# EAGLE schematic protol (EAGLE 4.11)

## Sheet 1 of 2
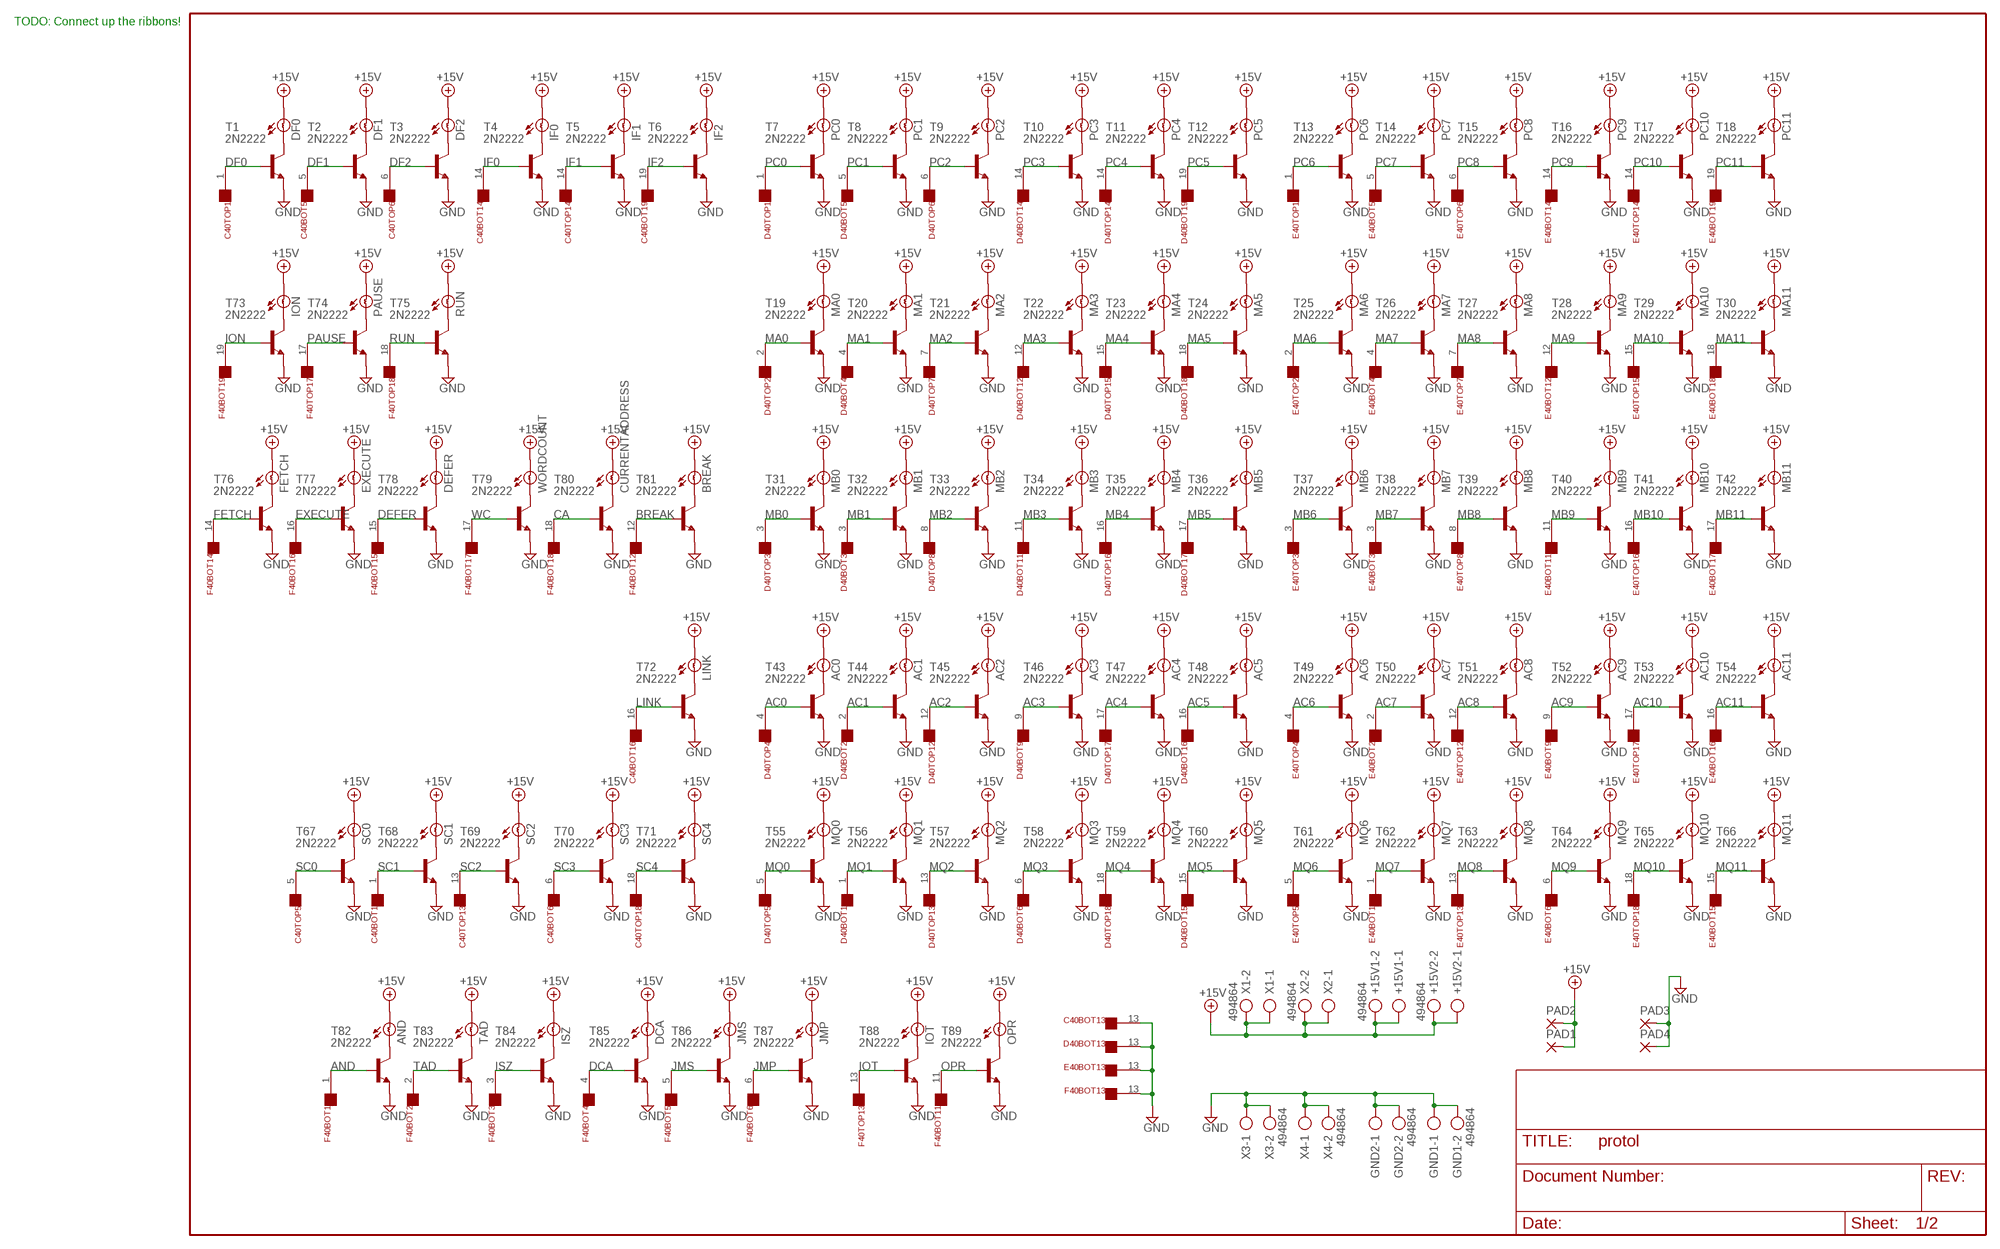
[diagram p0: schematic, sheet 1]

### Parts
+15V1  494864  AK500/2  [AK500/2]
+15V2  494864  AK500/2  [AK500/2]
AC0  BULB  [BULB]
AC1  BULB  [BULB]
AC2  BULB  [BULB]
AC3  BULB  [BULB]
AC4  BULB  [BULB]
AC5  BULB  [BULB]
AC6  BULB  [BULB]
AC7  BULB  [BULB]
AC8  BULB  [BULB]
AC9  BULB  [BULB]
AC10  BULB  [BULB]
AC11  BULB  [BULB]
AND  BULB  [BULB]
BREAK  BULB  [BULB]
C40BOT  FLEX19  [FLEX19]
C40TOP  FLEX19  [FLEX19]
CURRENTADDRESS  BULB  [BULB]
D40BOT  FLEX19  [FLEX19]
D40TOP  FLEX19  [FLEX19]
DCA  BULB  [BULB]
DEFER  BULB  [BULB]
DF0  BULB  [BULB]
DF1  BULB  [BULB]
DF2  BULB  [BULB]
E40BOT  FLEX19  [FLEX19]
E40TOP  FLEX19  [FLEX19]
EXECUTE  BULB  [BULB]
F40BOT  FLEX19  [FLEX19]
F40TOP  FLEX19  [FLEX19]
FETCH  BULB  [BULB]
GND1  494864  AK500/2  [AK500/2]
GND2  494864  AK500/2  [AK500/2]
IF0  BULB  [BULB]
IF1  BULB  [BULB]
IF2  BULB  [BULB]
ION  BULB  [BULB]
IOT  BULB  [BULB]
ISZ  BULB  [BULB]
JMP  BULB  [BULB]
JMS  BULB  [BULB]
LINK  BULB  [BULB]
MA0  BULB  [BULB]
MA1  BULB  [BULB]
MA2  BULB  [BULB]
MA3  BULB  [BULB]
MA4  BULB  [BULB]
MA5  BULB  [BULB]
MA6  BULB  [BULB]
MA7  BULB  [BULB]
MA8  BULB  [BULB]
MA9  BULB  [BULB]
MA10  BULB  [BULB]
MA11  BULB  [BULB]
MB0  BULB  [BULB]
MB1  BULB  [BULB]
MB2  BULB  [BULB]
MB3  BULB  [BULB]
MB4  BULB  [BULB]
MB5  BULB  [BULB]
MB6  BULB  [BULB]
MB7  BULB  [BULB]
MB8  BULB  [BULB]
MB9  BULB  [BULB]
MB10  BULB  [BULB]
MB11  BULB  [BULB]
MQ0  BULB  [BULB]
MQ1  BULB  [BULB]
MQ2  BULB  [BULB]
MQ3  BULB  [BULB]
MQ4  BULB  [BULB]
MQ5  BULB  [BULB]
MQ6  BULB  [BULB]
MQ7  BULB  [BULB]
MQ8  BULB  [BULB]
MQ9  BULB  [BULB]
MQ10  BULB  [BULB]
MQ11  BULB  [BULB]
OPR  BULB  [BULB]
PAD1  2,54/0,8  [2,54/0,8]
PAD2  2,54/0,8  [2,54/0,8]
PAD3  2,54/0,8  [2,54/0,8]
PAD4  2,54/0,8  [2,54/0,8]
PAUSE  BULB  [BULB]
PC0  BULB  [BULB]
PC1  BULB  [BULB]
PC2  BULB  [BULB]
PC3  BULB  [BULB]
PC4  BULB  [BULB]
PC5  BULB  [BULB]
PC6  BULB  [BULB]
PC7  BULB  [BULB]
PC8  BULB  [BULB]
PC9  BULB  [BULB]
PC10  BULB  [BULB]
PC11  BULB  [BULB]
RUN  BULB  [BULB]
SC0  BULB  [BULB]
SC1  BULB  [BULB]
SC2  BULB  [BULB]
SC3  BULB  [BULB]
SC4  BULB  [BULB]
T1  2N2222  -NPN-TO92  [TO92]
T2  2N2222  -NPN-TO92  [TO92]
T3  2N2222  -NPN-TO92  [TO92]
T4  2N2222  -NPN-TO92  [TO92]
T5  2N2222  -NPN-TO92  [TO92]
T6  2N2222  -NPN-TO92  [TO92]
T7  2N2222  -NPN-TO92  [TO92]
T8  2N2222  -NPN-TO92  [TO92]
T9  2N2222  -NPN-TO92  [TO92]
T10  2N2222  -NPN-TO92  [TO92]
T11  2N2222  -NPN-TO92  [TO92]
T12  2N2222  -NPN-TO92  [TO92]
T13  2N2222  -NPN-TO92  [TO92]
T14  2N2222  -NPN-TO92  [TO92]
T15  2N2222  -NPN-TO92  [TO92]
T16  2N2222  -NPN-TO92  [TO92]
T17  2N2222  -NPN-TO92  [TO92]
T18  2N2222  -NPN-TO92  [TO92]
T19  2N2222  -NPN-TO92  [TO92]
T20  2N2222  -NPN-TO92  [TO92]
T21  2N2222  -NPN-TO92  [TO92]
T22  2N2222  -NPN-TO92  [TO92]
T23  2N2222  -NPN-TO92  [TO92]
T24  2N2222  -NPN-TO92  [TO92]
T25  2N2222  -NPN-TO92  [TO92]
T26  2N2222  -NPN-TO92  [TO92]
T27  2N2222  -NPN-TO92  [TO92]
T28  2N2222  -NPN-TO92  [TO92]
T29  2N2222  -NPN-TO92  [TO92]
T30  2N2222  -NPN-TO92  [TO92]
T31  2N2222  -NPN-TO92  [TO92]
T32  2N2222  -NPN-TO92  [TO92]
T33  2N2222  -NPN-TO92  [TO92]
T34  2N2222  -NPN-TO92  [TO92]
T35  2N2222  -NPN-TO92  [TO92]
T36  2N2222  -NPN-TO92  [TO92]
T37  2N2222  -NPN-TO92  [TO92]
T38  2N2222  -NPN-TO92  [TO92]
T39  2N2222  -NPN-TO92  [TO92]
T40  2N2222  -NPN-TO92  [TO92]
T41  2N2222  -NPN-TO92  [TO92]
T42  2N2222  -NPN-TO92  [TO92]
T43  2N2222  -NPN-TO92  [TO92]
T44  2N2222  -NPN-TO92  [TO92]
T45  2N2222  -NPN-TO92  [TO92]
T46  2N2222  -NPN-TO92  [TO92]
T47  2N2222  -NPN-TO92  [TO92]
T48  2N2222  -NPN-TO92  [TO92]
T49  2N2222  -NPN-TO92  [TO92]
T50  2N2222  -NPN-TO92  [TO92]
T51  2N2222  -NPN-TO92  [TO92]
T52  2N2222  -NPN-TO92  [TO92]
T53  2N2222  -NPN-TO92  [TO92]
T54  2N2222  -NPN-TO92  [TO92]
T55  2N2222  -NPN-TO92  [TO92]
T56  2N2222  -NPN-TO92  [TO92]
T57  2N2222  -NPN-TO92  [TO92]
T58  2N2222  -NPN-TO92  [TO92]
T59  2N2222  -NPN-TO92  [TO92]
T60  2N2222  -NPN-TO92  [TO92]
T61  2N2222  -NPN-TO92  [TO92]
T62  2N2222  -NPN-TO92  [TO92]
T63  2N2222  -NPN-TO92  [TO92]
T64  2N2222  -NPN-TO92  [TO92]
T65  2N2222  -NPN-TO92  [TO92]
T66  2N2222  -NPN-TO92  [TO92]
T67  2N2222  -NPN-TO92  [TO92]
T68  2N2222  -NPN-TO92  [TO92]
T69  2N2222  -NPN-TO92  [TO92]
T70  2N2222  -NPN-TO92  [TO92]
T71  2N2222  -NPN-TO92  [TO92]
T72  2N2222  -NPN-TO92  [TO92]
T73  2N2222  -NPN-TO92  [TO92]
T74  2N2222  -NPN-TO92  [TO92]
T75  2N2222  -NPN-TO92  [TO92]
T76  2N2222  -NPN-TO92  [TO92]
T77  2N2222  -NPN-TO92  [TO92]
T78  2N2222  -NPN-TO92  [TO92]
T79  2N2222  -NPN-TO92  [TO92]
T80  2N2222  -NPN-TO92  [TO92]
T81  2N2222  -NPN-TO92  [TO92]
T82  2N2222  -NPN-TO92  [TO92]
T83  2N2222  -NPN-TO92  [TO92]
T84  2N2222  -NPN-TO92  [TO92]
T85  2N2222  -NPN-TO92  [TO92]
T86  2N2222  -NPN-TO92  [TO92]
T87  2N2222  -NPN-TO92  [TO92]
T88  2N2222  -NPN-TO92  [TO92]
T89  2N2222  -NPN-TO92  [TO92]
TAD  BULB  [BULB]
WORDCOUNT  BULB  [BULB]
X1  494864  AK500/2  [AK500/2]
X2  494864  AK500/2  [AK500/2]
X3  494864  AK500/2  [AK500/2]
X4  494864  AK500/2  [AK500/2]

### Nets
+15V [supply]: +15V1.1 +15V1.2 +15V2.1 +15V2.2 AC0.A AC1.A AC2.A AC3.A AC4.A AC5.A AC6.A AC7.A AC8.A AC9.A AC10.A AC11.A AND.A BREAK.A CURRENTADDRESS.A DCA.A DEFER.A DF0.A DF1.A DF2.A EXECUTE.A FETCH.A IF0.A IF1.A IF2.A ION.A IOT.A ISZ.A JMP.A JMS.A LINK.A MA0.A MA1.A MA2.A MA3.A MA4.A MA5.A MA6.A MA7.A MA8.A MA9.A MA10.A MA11.A MB0.A MB1.A MB2.A MB3.A MB4.A MB5.A MB6.A MB7.A MB8.A MB9.A MB10.A MB11.A MQ0.A MQ1.A MQ2.A MQ3.A MQ4.A MQ5.A MQ6.A MQ7.A MQ8.A MQ9.A MQ10.A MQ11.A OPR.A PAD1.1(P) PAD2.1(P) PAUSE.A PC0.A PC1.A PC2.A PC3.A PC4.A PC5.A PC6.A PC7.A PC8.A PC9.A PC10.A PC11.A RUN.A SC0.A SC1.A SC2.A SC3.A SC4.A TAD.A WORDCOUNT.A X1.1 X1.2 X2.1 X2.2
AC0: D40TOP.4 T43.2(B) ; also sheet 2
AC1: D40BOT.2 T44.2(B) ; also sheet 2
AC2: D40TOP.12 T45.2(B) ; also sheet 2
AC3: D40BOT.9 T46.2(B) ; also sheet 2
AC4: D40TOP.17 T47.2(B) ; also sheet 2
AC5: D40BOT.16 T48.2(B) ; also sheet 2
AC6: E40TOP.4 T49.2(B) ; also sheet 2
AC7: E40BOT.2 T50.2(B) ; also sheet 2
AC8: E40TOP.12 T51.2(B) ; also sheet 2
AC9: E40BOT.9 T52.2(B) ; also sheet 2
AC10: E40TOP.17 T53.2(B) ; also sheet 2
AC11: E40BOT.16 T54.2(B) ; also sheet 2
AND: F40BOT.1 T82.2(B) ; also sheet 2
BREAK: F40BOT.12 T81.2(B) ; also sheet 2
CA: F40BOT.18 T80.2(B) ; also sheet 2
DCA: F40BOT.4 T85.2(B) ; also sheet 2
DEFER: F40BOT.15 T78.2(B) ; also sheet 2
DF0: C40TOP.1 T1.2(B) ; also sheet 2
DF1: C40BOT.5 T2.2(B) ; also sheet 2
DF2: C40TOP.6 T3.2(B) ; also sheet 2
EXECUTE: F40BOT.16 T77.2(B) ; also sheet 2
FETCH: F40BOT.14 T76.2(B) ; also sheet 2
GND [supply]: C40BOT.13 D40BOT.13 E40BOT.13 F40BOT.13 GND1.1 GND1.2 GND2.1 GND2.2 PAD3.1(P) PAD4.1(P) T1.1(E) T2.1(E) T3.1(E) T4.1(E) T5.1(E) T6.1(E) T7.1(E) T8.1(E) T9.1(E) T10.1(E) T11.1(E) T12.1(E) T13.1(E) T14.1(E) T15.1(E) T16.1(E) T17.1(E) T18.1(E) T19.1(E) T20.1(E) T21.1(E) T22.1(E) T23.1(E) T24.1(E) T25.1(E) T26.1(E) T27.1(E) T28.1(E) T29.1(E) T30.1(E) T31.1(E) T32.1(E) T33.1(E) T34.1(E) T35.1(E) T36.1(E) T37.1(E) T38.1(E) T39.1(E) T40.1(E) T41.1(E) T42.1(E) T43.1(E) T44.1(E) T45.1(E) T46.1(E) T47.1(E) T48.1(E) T49.1(E) T50.1(E) T51.1(E) T52.1(E) T53.1(E) T54.1(E) T55.1(E) T56.1(E) T57.1(E) T58.1(E) T59.1(E) T60.1(E) T61.1(E) T62.1(E) T63.1(E) T64.1(E) T65.1(E) T66.1(E) T67.1(E) T68.1(E) T69.1(E) T70.1(E) T71.1(E) T72.1(E) T73.1(E) T74.1(E) T75.1(E) T76.1(E) T77.1(E) T78.1(E) T79.1(E) T80.1(E) T81.1(E) T82.1(E) T83.1(E) T84.1(E) T85.1(E) T86.1(E) T87.1(E) T88.1(E) T89.1(E) X3.1 X3.2 X4.1 X4.2 ; also sheet 2
IF0: C40BOT.14 T4.2(B) ; also sheet 2
IF1: C40TOP.14 T5.2(B) ; also sheet 2
IF2: C40BOT.19 T6.2(B) ; also sheet 2
ION: F40BOT.19 T73.2(B) ; also sheet 2
IOT: F40TOP.13 T88.2(B) ; also sheet 2
ISZ: F40BOT.3 T84.2(B) ; also sheet 2
JMP: F40BOT.6 T87.2(B) ; also sheet 2
JMS: F40BOT.5 T86.2(B) ; also sheet 2
LINK: C40BOT.16 T72.2(B) ; also sheet 2
MA0: D40TOP.2 T19.2(B) ; also sheet 2
MA1: D40BOT.4 T20.2(B) ; also sheet 2
MA2: D40TOP.7 T21.2(B) ; also sheet 2
MA3: D40BOT.12 T22.2(B) ; also sheet 2
MA4: D40TOP.15 T23.2(B) ; also sheet 2
MA5: D40BOT.18 T24.2(B) ; also sheet 2
MA6: E40TOP.2 T25.2(B) ; also sheet 2
MA7: E40BOT.4 T26.2(B) ; also sheet 2
MA8: E40TOP.7 T27.2(B) ; also sheet 2
MA9: E40BOT.12 T28.2(B) ; also sheet 2
MA10: E40TOP.15 T29.2(B) ; also sheet 2
MA11: E40BOT.18 T30.2(B) ; also sheet 2
MB0: D40TOP.3 T31.2(B) ; also sheet 2
MB1: D40BOT.3 T32.2(B) ; also sheet 2
MB2: D40TOP.8 T33.2(B) ; also sheet 2
MB3: D40BOT.11 T34.2(B) ; also sheet 2
MB4: D40TOP.16 T35.2(B) ; also sheet 2
MB5: D40BOT.17 T36.2(B) ; also sheet 2
MB6: E40TOP.3 T37.2(B) ; also sheet 2
MB7: E40BOT.3 T38.2(B) ; also sheet 2
MB8: E40TOP.8 T39.2(B) ; also sheet 2
MB9: E40BOT.11 T40.2(B) ; also sheet 2
MB10: E40TOP.16 T41.2(B) ; also sheet 2
MB11: E40BOT.17 T42.2(B) ; also sheet 2
MQ0: D40TOP.5 T55.2(B) ; also sheet 2
MQ1: D40BOT.1 T56.2(B) ; also sheet 2
MQ2: D40TOP.13 T57.2(B) ; also sheet 2
MQ3: D40BOT.6 T58.2(B) ; also sheet 2
MQ4: D40TOP.18 T59.2(B) ; also sheet 2
MQ5: D40BOT.15 T60.2(B) ; also sheet 2
MQ6: E40TOP.5 T61.2(B) ; also sheet 2
MQ7: E40BOT.1 T62.2(B) ; also sheet 2
MQ8: E40TOP.13 T63.2(B) ; also sheet 2
MQ9: E40BOT.6 T64.2(B) ; also sheet 2
MQ10: E40TOP.18 T65.2(B) ; also sheet 2
MQ11: E40BOT.15 T66.2(B) ; also sheet 2
N$1: DF0.B T1.3(C)
N$2: DF1.B T2.3(C)
N$3: DF2.B T3.3(C)
N$4: IF0.B T4.3(C)
N$5: IF1.B T5.3(C)
N$6: IF2.B T6.3(C)
N$7: PC0.B T7.3(C)
N$8: PC1.B T8.3(C)
N$9: PC2.B T9.3(C)
N$10: PC3.B T10.3(C)
N$11: PC4.B T11.3(C)
N$12: PC5.B T12.3(C)
N$13: PC6.B T13.3(C)
N$14: PC7.B T14.3(C)
N$15: PC8.B T15.3(C)
N$16: PC9.B T16.3(C)
N$17: PC10.B T17.3(C)
N$18: PC11.B T18.3(C)
N$19: MA0.B T19.3(C)
N$20: MA1.B T20.3(C)
N$21: MA2.B T21.3(C)
N$22: MA3.B T22.3(C)
N$23: MA4.B T23.3(C)
N$24: MA5.B T24.3(C)
N$25: MA6.B T25.3(C)
N$26: MA7.B T26.3(C)
N$27: MA8.B T27.3(C)
N$28: MA9.B T28.3(C)
N$29: MA10.B T29.3(C)
N$30: MA11.B T30.3(C)
N$31: MB0.B T31.3(C)
N$32: MB1.B T32.3(C)
N$33: MB2.B T33.3(C)
N$34: MB3.B T34.3(C)
N$35: MB4.B T35.3(C)
N$36: MB5.B T36.3(C)
N$37: MB6.B T37.3(C)
N$38: MB7.B T38.3(C)
N$39: MB8.B T39.3(C)
N$40: MB9.B T40.3(C)
N$41: MB10.B T41.3(C)
N$42: MB11.B T42.3(C)
N$43: AC0.B T43.3(C)
N$44: AC1.B T44.3(C)
N$45: AC2.B T45.3(C)
N$46: AC3.B T46.3(C)
N$47: AC4.B T47.3(C)
N$48: AC5.B T48.3(C)
N$49: AC6.B T49.3(C)
N$50: AC7.B T50.3(C)
N$51: AC8.B T51.3(C)
N$52: AC9.B T52.3(C)
N$53: AC10.B T53.3(C)
N$54: AC11.B T54.3(C)
N$55: MQ0.B T55.3(C)
N$56: MQ1.B T56.3(C)
N$57: MQ2.B T57.3(C)
N$58: MQ3.B T58.3(C)
N$59: MQ4.B T59.3(C)
N$60: MQ5.B T60.3(C)
N$61: MQ6.B T61.3(C)
N$62: MQ7.B T62.3(C)
N$63: MQ8.B T63.3(C)
N$64: MQ9.B T64.3(C)
N$65: MQ10.B T65.3(C)
N$66: MQ11.B T66.3(C)
N$67: SC0.B T67.3(C)
N$68: SC1.B T68.3(C)
N$69: SC2.B T69.3(C)
N$70: SC3.B T70.3(C)
N$71: SC4.B T71.3(C)
N$72: LINK.B T72.3(C)
N$73: ION.B T73.3(C)
N$74: PAUSE.B T74.3(C)
N$75: RUN.B T75.3(C)
N$76: FETCH.B T76.3(C)
N$77: EXECUTE.B T77.3(C)
N$78: DEFER.B T78.3(C)
N$79: T79.3(C) WORDCOUNT.B
N$80: CURRENTADDRESS.B T80.3(C)
N$81: BREAK.B T81.3(C)
N$82: AND.B T82.3(C)
N$83: T83.3(C) TAD.B
N$84: ISZ.B T84.3(C)
N$85: DCA.B T85.3(C)
N$86: JMS.B T86.3(C)
N$87: JMP.B T87.3(C)
N$88: IOT.B T88.3(C)
N$89: OPR.B T89.3(C)
OPR: F40BOT.11 T89.2(B) ; also sheet 2
PAUSE: F40TOP.17 T74.2(B) ; also sheet 2
PC0: D40TOP.1 T7.2(B) ; also sheet 2
PC1: D40BOT.5 T8.2(B) ; also sheet 2
PC2: D40TOP.6 T9.2(B) ; also sheet 2
PC3: D40BOT.14 T10.2(B) ; also sheet 2
PC4: D40TOP.14 T11.2(B) ; also sheet 2
PC5: D40BOT.19 T12.2(B) ; also sheet 2
PC6: E40TOP.1 T13.2(B) ; also sheet 2
PC7: E40BOT.5 T14.2(B) ; also sheet 2
PC8: E40TOP.6 T15.2(B) ; also sheet 2
PC9: E40BOT.14 T16.2(B) ; also sheet 2
PC10: E40TOP.14 T17.2(B) ; also sheet 2
PC11: E40BOT.19 T18.2(B) ; also sheet 2
RUN: F40TOP.18 T75.2(B) ; also sheet 2
SC0: C40TOP.5 T67.2(B) ; also sheet 2
SC1: C40BOT.1 T68.2(B) ; also sheet 2
SC2: C40TOP.13 T69.2(B) ; also sheet 2
SC3: C40BOT.6 T70.2(B) ; also sheet 2
SC4: C40TOP.18 T71.2(B) ; also sheet 2
TAD: F40BOT.2 T83.2(B) ; also sheet 2
WC: F40BOT.17 T79.2(B) ; also sheet 2
Unconnected: C40BOT.2 C40BOT.3 C40BOT.4 C40BOT.7 C40BOT.8 C40BOT.9 C40BOT.10 C40BOT.11 C40BOT.12 C40BOT.15 C40BOT.17 C40BOT.18 C40TOP.2 C40TOP.3 C40TOP.4 C40TOP.7 C40TOP.8 C40TOP.9 C40TOP.10 C40TOP.11 C40TOP.12 C40TOP.15 C40TOP.16 C40TOP.17 C40TOP.19 D40BOT.7 D40BOT.8 D40BOT.10 D40TOP.9 D40TOP.10 D40TOP.11 D40TOP.19 E40BOT.7 E40BOT.8 E40BOT.10 E40TOP.9 E40TOP.10 E40TOP.11 E40TOP.19 F40BOT.7 F40BOT.8 F40BOT.9 F40BOT.10 F40TOP.1 F40TOP.2 F40TOP.3 F40TOP.4 F40TOP.5 F40TOP.6 F40TOP.7 F40TOP.8 F40TOP.9 F40TOP.10 F40TOP.11 F40TOP.12 F40TOP.14 F40TOP.15 F40TOP.16 F40TOP.19

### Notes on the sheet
- TODO: Connect up the ribbons!

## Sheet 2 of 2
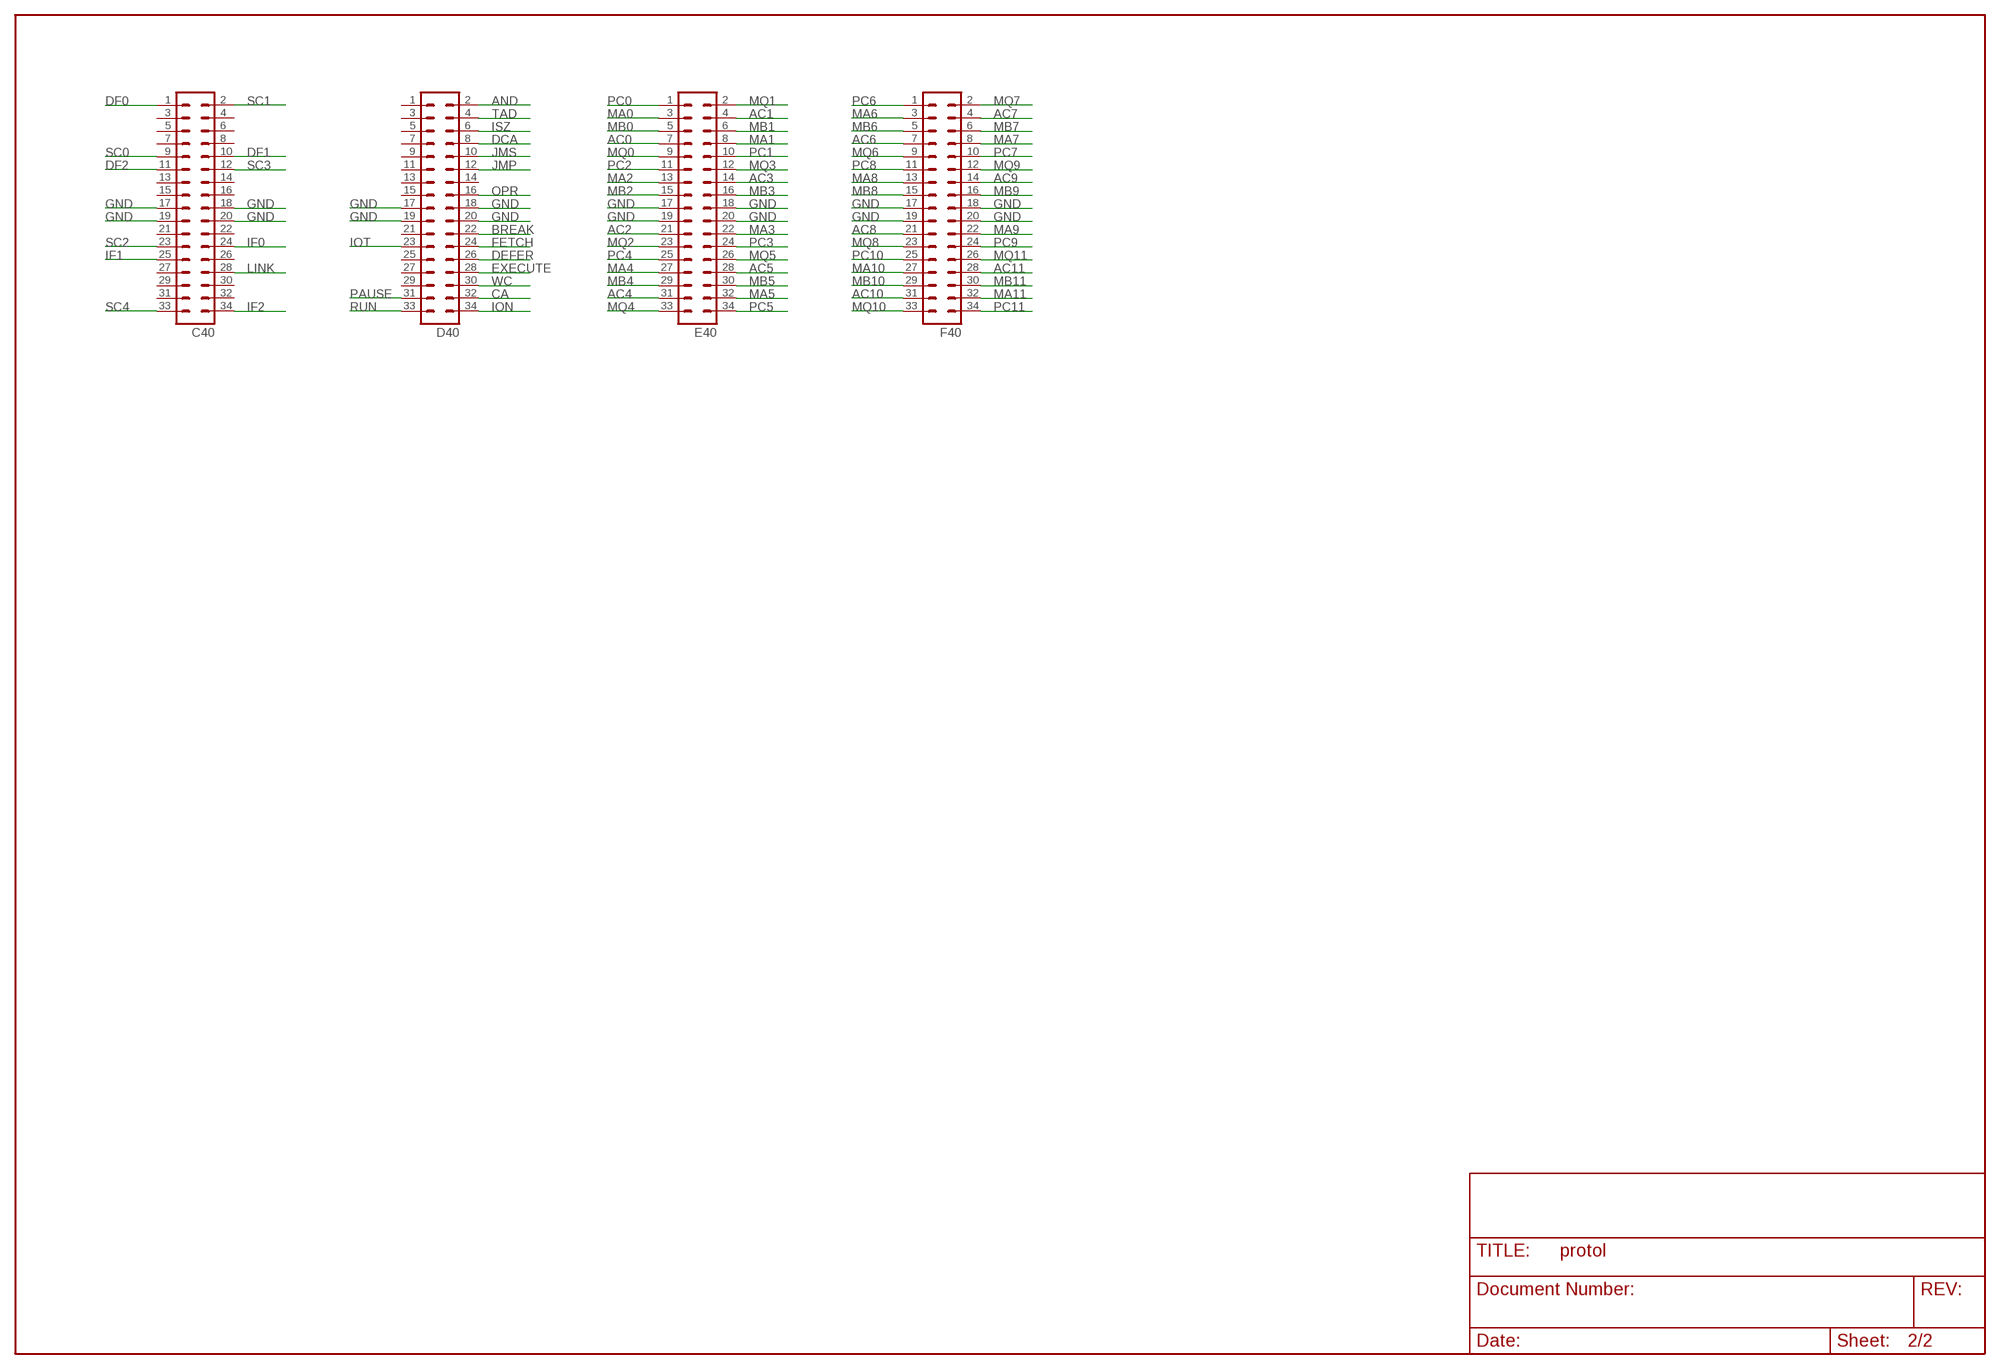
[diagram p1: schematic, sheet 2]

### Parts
C40  MA17-2  [MA17-2]
D40  MA17-2  [MA17-2]
E40  MA17-2  [MA17-2]
F40  MA17-2  [MA17-2]

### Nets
AC0: E40.7 ; also sheet 1
AC1: E40.4 ; also sheet 1
AC2: E40.21 ; also sheet 1
AC3: E40.14 ; also sheet 1
AC4: E40.31 ; also sheet 1
AC5: E40.28 ; also sheet 1
AC6: F40.7 ; also sheet 1
AC7: F40.4 ; also sheet 1
AC8: F40.21 ; also sheet 1
AC9: F40.14 ; also sheet 1
AC10: F40.31 ; also sheet 1
AC11: F40.28 ; also sheet 1
AND: D40.2 ; also sheet 1
BREAK: D40.22 ; also sheet 1
CA: D40.32 ; also sheet 1
DCA: D40.8 ; also sheet 1
DEFER: D40.26 ; also sheet 1
DF0: C40.1 ; also sheet 1
DF1: C40.10 ; also sheet 1
DF2: C40.11 ; also sheet 1
EXECUTE: D40.28 ; also sheet 1
FETCH: D40.24 ; also sheet 1
GND [supply]: C40.17 C40.18 C40.19 C40.20 D40.17 D40.18 D40.19 D40.20 E40.17 E40.18 E40.19 E40.20 F40.17 F40.18 F40.19 F40.20 ; also sheet 1
IF0: C40.24 ; also sheet 1
IF1: C40.25 ; also sheet 1
IF2: C40.34 ; also sheet 1
ION: D40.34 ; also sheet 1
IOT: D40.23 ; also sheet 1
ISZ: D40.6 ; also sheet 1
JMP: D40.12 ; also sheet 1
JMS: D40.10 ; also sheet 1
LINK: C40.28 ; also sheet 1
MA0: E40.3 ; also sheet 1
MA1: E40.8 ; also sheet 1
MA2: E40.13 ; also sheet 1
MA3: E40.22 ; also sheet 1
MA4: E40.27 ; also sheet 1
MA5: E40.32 ; also sheet 1
MA6: F40.3 ; also sheet 1
MA7: F40.8 ; also sheet 1
MA8: F40.13 ; also sheet 1
MA9: F40.22 ; also sheet 1
MA10: F40.27 ; also sheet 1
MA11: F40.32 ; also sheet 1
MB0: E40.5 ; also sheet 1
MB1: E40.6 ; also sheet 1
MB2: E40.15 ; also sheet 1
MB3: E40.16 ; also sheet 1
MB4: E40.29 ; also sheet 1
MB5: E40.30 ; also sheet 1
MB6: F40.5 ; also sheet 1
MB7: F40.6 ; also sheet 1
MB8: F40.15 ; also sheet 1
MB9: F40.16 ; also sheet 1
MB10: F40.29 ; also sheet 1
MB11: F40.30 ; also sheet 1
MQ0: E40.9 ; also sheet 1
MQ1: E40.2 ; also sheet 1
MQ2: E40.23 ; also sheet 1
MQ3: E40.12 ; also sheet 1
MQ4: E40.33 ; also sheet 1
MQ5: E40.26 ; also sheet 1
MQ6: F40.9 ; also sheet 1
MQ7: F40.2 ; also sheet 1
MQ8: F40.23 ; also sheet 1
MQ9: F40.12 ; also sheet 1
MQ10: F40.33 ; also sheet 1
MQ11: F40.26 ; also sheet 1
OPR: D40.16 ; also sheet 1
PAUSE: D40.31 ; also sheet 1
PC0: E40.1 ; also sheet 1
PC1: E40.10 ; also sheet 1
PC2: E40.11 ; also sheet 1
PC3: E40.24 ; also sheet 1
PC4: E40.25 ; also sheet 1
PC5: E40.34 ; also sheet 1
PC6: F40.1 ; also sheet 1
PC7: F40.10 ; also sheet 1
PC8: F40.11 ; also sheet 1
PC9: F40.24 ; also sheet 1
PC10: F40.25 ; also sheet 1
PC11: F40.34 ; also sheet 1
RUN: D40.33 ; also sheet 1
SC0: C40.9 ; also sheet 1
SC1: C40.2 ; also sheet 1
SC2: C40.23 ; also sheet 1
SC3: C40.12 ; also sheet 1
SC4: C40.33 ; also sheet 1
TAD: D40.4 ; also sheet 1
WC: D40.30 ; also sheet 1
Unconnected: C40.3 C40.4 C40.5 C40.6 C40.7 C40.8 C40.13 C40.14 C40.15 C40.16 C40.21 C40.22 C40.26 C40.27 C40.29 C40.30 C40.31 C40.32 D40.1 D40.3 D40.5 D40.7 D40.9 D40.11 D40.13 D40.14 D40.15 D40.21 D40.25 D40.27 D40.29

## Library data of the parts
+15V1 +15V2 GND1 GND2 X1-X4 = con-ptr500:AK500/2: CONNECTOR
AC0 AC1-AC11 AND BREAK CURRENTADDRESS DCA DEFER DF0 DF1 DF2 EXECUTE FETCH IF0 IF1 IF2 ION IOT ISZ JMP JMS LINK MA0 MA1-MA11 MB0 MB1-MB11 MQ0 MQ1-MQ11 OPR PAUSE PC0 PC1-PC11 RUN SC0 SC1-SC4 TAD WORDCOUNT = dec-con:BULB: LED
C40 D40 E40 F40 = con-lstb:MA17-2: PIN HEADER
C40BOT C40TOP D40BOT D40TOP E40BOT E40TOP F40BOT F40TOP = dec-con:FLEX19
PAD1-PAD4 = wirepad:2,54/0,8: THROUGH-HOLE PAD
T1-T89 = transistor:*-NPN-: NPN Transistror

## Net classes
1 supply: width 0.762 mm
